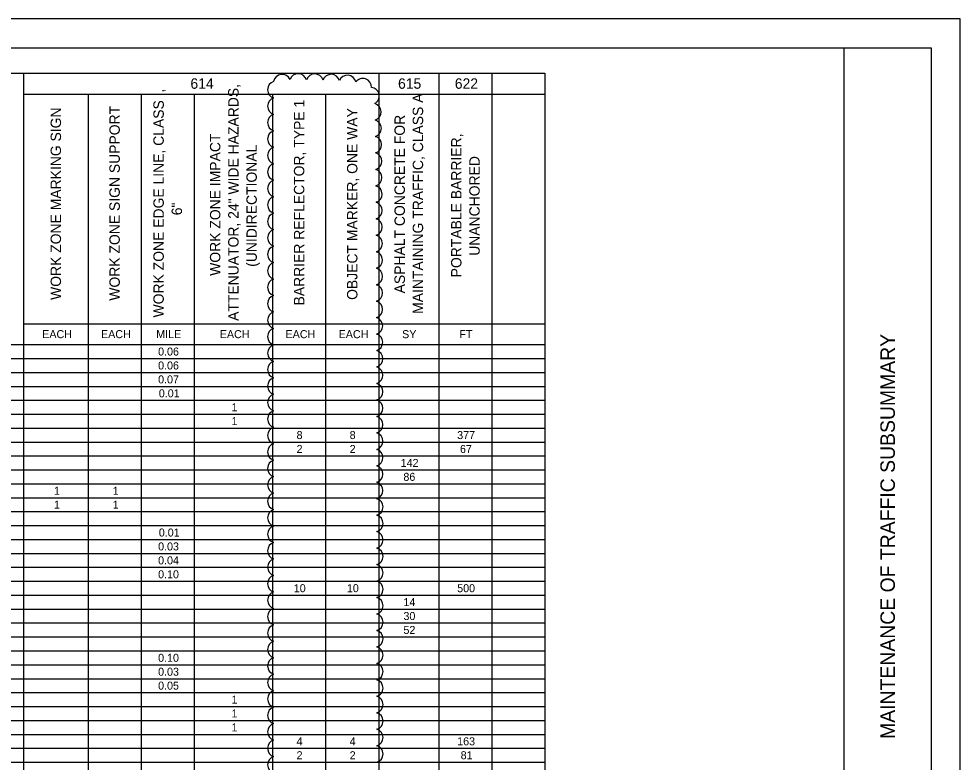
# Model space of a CAD drawing. Extents: x 0 to 35.9, y 0 to 22.
# Drawn here: x 17.78 to 34, y 9.18 to 22 of the extents above; entities that cross this region are included whole.
import ezdxf

# ---------------------------------------------------------------- set-up
doc = ezdxf.new("R2010")
doc.units = 0
for name, color, linetype in [('SC_Scratch2', 7, 'Continuous'), ('SH_Border', 7, 'Continuous'), ('SH_Cut_Line', 7, 'Continuous'), ('SH_Data', 7, 'Continuous'), ('SH_Text', 7, 'Continuous')]:
    doc.layers.add(name, color=color, linetype=linetype)

msp = doc.modelspace()

# ---------------------------------------------------------------- linework, layer by layer
at = {"layer": 'SC_Scratch2'}
for centre, start, end in [((22.315, 20.892), 23.859, 168.859), ((22.593, 20.905), 16.7934, 161.7934), ((22.877, 20.901), 16.6477, 161.6477), ((23.16, 20.894), 15.5399, 160.5399), ((23.441, 20.878), 12.7492, 157.7492), ((23.705, 20.822), 358.2571, 143.2571), ((22.214, 20.778), 107.5, 252.5), ((23.839, 20.669), 299.4005, 84.4005), ((22.214, 20.494), 107.5, 252.5), ((23.871, 20.396), 288.8288, 73.8288), ((22.214, 20.211), 107.5, 252.5), ((23.876, 20.113), 288.4136, 73.4136), ((22.214, 19.927), 107.5, 252.5), ((23.88, 19.829), 288.2088, 73.2088), ((22.214, 19.643), 107.5, 252.5), ((23.884, 19.545), 288.0806, 73.0806), ((22.214, 19.359), 107.5, 252.5), ((23.886, 19.261), 287.9905, 72.9905), ((22.214, 19.075), 107.5, 252.5), ((23.889, 18.978), 287.9228, 72.9228), ((22.214, 18.791), 107.5, 252.5), ((23.891, 18.694), 287.8694, 72.8694), ((22.214, 18.507), 107.5, 252.5), ((23.892, 18.41), 287.826, 72.826), ((22.214, 18.223), 107.5, 252.5), ((23.894, 18.126), 287.7897, 72.7897), ((22.214, 17.939), 107.5, 252.5), ((23.895, 17.842), 287.7588, 72.7588), ((22.214, 17.655), 107.5, 252.5), ((23.896, 17.558), 287.7321, 72.7321), ((22.214, 17.371), 107.5, 252.5), ((23.897, 17.274), 287.7088, 72.7088), ((22.214, 17.088), 107.5, 252.5), ((23.898, 16.99), 287.6881, 72.6881), ((22.214, 16.804), 107.5, 252.5), ((23.899, 16.707), 287.6696, 72.6696), ((22.214, 16.52), 107.5, 252.5), ((23.9, 16.423), 287.6529, 72.6529), ((22.214, 16.236), 107.5, 252.5), ((23.901, 16.139), 287.6378, 72.6378), ((22.214, 15.952), 107.5, 252.5), ((23.901, 15.855), 287.6241, 72.6241), ((22.214, 15.668), 107.5, 252.5), ((23.902, 15.571), 287.6114, 72.6114), ((22.214, 15.384), 107.5, 252.5), ((23.903, 15.287), 287.5998, 72.5998), ((22.214, 15.1), 107.5, 252.5), ((23.903, 15.003), 287.589, 72.589), ((22.214, 14.816), 107.5, 252.5), ((23.903, 14.719), 287.579, 72.579), ((22.214, 14.532), 107.5, 252.5), ((23.904, 14.435), 287.5697, 72.5697), ((22.214, 14.249), 107.5, 252.5), ((23.904, 14.151), 287.561, 72.561), ((22.214, 13.965), 107.5, 252.5), ((23.904, 13.868), 287.5528, 72.5528), ((22.214, 13.681), 107.5, 252.5), ((23.905, 13.584), 287.5451, 72.5451), ((22.214, 13.397), 107.5, 252.5), ((23.905, 13.3), 287.5378, 72.5378), ((22.214, 13.113), 107.5, 252.5), ((23.905, 13.016), 287.531, 72.531), ((22.214, 12.829), 107.5, 252.5), ((23.905, 12.732), 287.5245, 72.5245), ((22.214, 12.545), 107.5, 252.5), ((23.905, 12.448), 287.5184, 72.5184), ((22.214, 12.261), 107.5, 252.5), ((23.905, 12.164), 287.5125, 72.5125), ((22.214, 11.977), 107.5, 252.5), ((23.905, 11.88), 287.507, 72.507), ((22.214, 11.693), 107.5, 252.5), ((23.905, 11.596), 287.5018, 72.5018), ((22.214, 11.409), 107.5, 252.5), ((23.905, 11.312), 287.5, 72.5), ((22.214, 11.126), 107.5, 252.5), ((23.905, 11.029), 287.5, 72.5), ((22.214, 10.842), 107.5, 252.5), ((23.905, 10.745), 287.5, 72.5), ((22.214, 10.558), 107.5, 252.5), ((23.905, 10.461), 287.5, 72.5), ((22.214, 10.274), 107.5, 252.5), ((23.905, 10.177), 287.5, 72.5), ((22.214, 9.99), 107.5, 252.5), ((23.905, 9.893), 287.5, 72.5), ((22.214, 9.706), 107.5, 252.5), ((23.905, 9.609), 287.5, 72.5), ((22.214, 9.422), 107.5, 252.5), ((23.905, 9.325), 287.5, 72.5), ((22.214, 9.138), 107.5, 252.5)]:
    msp.add_arc(centre, 0.149, start, end, dxfattribs=at)
at = {"layer": 'SH_Border'}
msp.add_line((32, 0.5), (32, 21.5), dxfattribs=at)
msp.add_lwpolyline([(1.5, 21.5), (33.5, 21.5), (33.5, 0.5), (1.5, 0.5)], close=True, dxfattribs=at)
at = {"layer": 'SH_Cut_Line'}
msp.add_lwpolyline([(0, 0), (34, 0), (34, 22), (0, 22)], close=True, dxfattribs=at)
at = {"layer": 'SH_Text'}
for p, q in [((10.03, 21.063), (26.845, 21.063)), ((17.86, 21.063), (17.86, 0.888)), ((23.98, 21.063), (23.98, 0.888)), ((25.015, 21.063), (25.015, 0.888)), ((25.93, 21.063), (25.93, 0.888)), ((26.845, 21.063), (26.845, 0.888)), ((17.86, 20.703), (26.845, 20.703)), ((18.97, 20.703), (18.97, 0.888)), ((19.885, 20.703), (19.885, 0.888)), ((20.8, 20.703), (20.8, 0.888)), ((22.15, 20.703), (22.15, 0.888)), ((23.065, 20.703), (23.065, 0.888)), ((17.86, 16.743), (26.845, 16.743)), ((10.03, 16.383), (26.845, 16.383)), ((10.03, 16.143), (26.845, 16.143)), ((10.03, 15.903), (26.845, 15.903)), ((10.03, 15.663), (26.845, 15.663)), ((10.03, 15.423), (26.845, 15.423)), ((10.03, 15.183), (26.845, 15.183)), ((10.03, 14.943), (26.845, 14.943)), ((10.03, 14.703), (26.845, 14.703)), ((10.03, 14.463), (26.845, 14.463)), ((10.03, 14.223), (26.845, 14.223)), ((10.03, 13.983), (26.845, 13.983)), ((10.03, 13.743), (26.845, 13.743)), ((10.03, 13.503), (26.845, 13.503)), ((10.03, 13.263), (26.845, 13.263)), ((10.03, 13.023), (26.845, 13.023)), ((10.03, 12.783), (26.845, 12.783)), ((10.03, 12.543), (26.845, 12.543)), ((10.03, 12.303), (26.845, 12.303)), ((10.03, 12.063), (26.845, 12.063)), ((10.03, 11.823), (26.845, 11.823)), ((10.03, 11.583), (26.845, 11.583)), ((10.03, 11.343), (26.845, 11.343)), ((10.03, 11.103), (26.845, 11.103)), ((10.03, 10.863), (26.845, 10.863)), ((10.03, 10.623), (26.845, 10.623)), ((10.03, 10.383), (26.845, 10.383)), ((10.03, 10.143), (26.845, 10.143)), ((10.03, 9.903), (26.845, 9.903)), ((10.03, 9.663), (26.845, 9.663)), ((10.03, 9.423), (26.845, 9.423)), ((10.03, 9.183), (26.845, 9.183))]:
    msp.add_line(p, q, dxfattribs=at)

# ---------------------------------------------------------------- texts
at = {"layer": 'SH_Data'}
msp.add_text('MAINTENANCE OF TRAFFIC SUBSUMMARY', height=0.25, rotation=90, dxfattribs=at).set_placement((32.875, 9.584))
at = {"layer": 'SH_Text'}
for s, height, p in [('614', 0.1794, (20.735, 20.794)), ('615', 0.1794, (24.313, 20.794)), ('622', 0.1794, (25.291, 20.794)), ('EACH', 0.138, (18.181, 16.494)), ('EACH', 0.138, (19.194, 16.494)), ('MILE', 0.138, (20.145, 16.494)), ('EACH', 0.138, (21.241, 16.494)), ('EACH', 0.138, (22.374, 16.494)), ('EACH', 0.138, (23.289, 16.494)), ('SY', 0.138, (24.383, 16.494)), ('FT', 0.138, (25.369, 16.494)), ('0.06', 0.138, (20.178, 16.194)), ('0.06', 0.138, (20.178, 15.954)), ('0.07', 0.138, (20.178, 15.714)), ('0.01', 0.138, (20.19, 15.474)), ('1', 0.138, (21.443, 15.234)), ('1', 0.138, (21.443, 14.994)), ('8', 0.138, (22.564, 14.754)), ('8', 0.138, (23.479, 14.754)), ('377', 0.138, (25.332, 14.754)), ('2', 0.138, (22.564, 14.514)), ('2', 0.138, (23.479, 14.514)), ('67', 0.138, (25.38, 14.514)), ('142', 0.138, (24.358, 14.274)), ('86', 0.138, (24.405, 14.034)), ('1', 0.138, (18.383, 13.794)), ('1', 0.138, (19.396, 13.794)), ('1', 0.138, (18.383, 13.554)), ('1', 0.138, (19.396, 13.554)), ('0.01', 0.138, (20.19, 13.074)), ('0.03', 0.138, (20.178, 12.834)), ('0.04', 0.138, (20.178, 12.594)), ('0.10', 0.138, (20.178, 12.354)), ('10', 0.138, (22.516, 12.114)), ('10', 0.138, (23.431, 12.114)), ('500', 0.138, (25.332, 12.114)), ('14', 0.138, (24.406, 11.874)), ('30', 0.138, (24.406, 11.634)), ('52', 0.138, (24.406, 11.394)), ('0.10', 0.138, (20.178, 10.914)), ('0.03', 0.138, (20.178, 10.674)), ('0.05', 0.138, (20.178, 10.434)), ('1', 0.138, (21.443, 10.194)), ('1', 0.138, (21.443, 9.954)), ('1', 0.138, (21.443, 9.714)), ('4', 0.138, (22.564, 9.474)), ('4', 0.138, (23.479, 9.474)), ('163', 0.138, (25.332, 9.474)), ('2', 0.138, (22.564, 9.234)), ('2', 0.138, (23.479, 9.234)), ('81', 0.138, (25.392, 9.234))]:
    msp.add_text(s, height=height, dxfattribs=at).set_placement(p)
for s, p in [('WORK ZONE EDGE LINE, CLASS I, ', (20.276, 16.851)), ('ATTENUATOR, 24" WIDE HAZARDS, ', (21.565, 16.792)), ('MAINTAINING TRAFFIC, CLASS A', (24.745, 16.913)), ('WORK ZONE MARKING SIGN', (18.505, 17.153)), ('WORK ZONE SIGN SUPPORT', (19.518, 17.14)), ('BARRIER REFLECTOR, TYPE 1', (22.698, 17.058)), ('OBJECT MARKER, ONE WAY', (23.613, 17.154)), ('ASPHALT CONCRETE FOR ', (24.431, 17.266)), ('WORK ZONE IMPACT ', (21.251, 17.569)), ('PORTABLE BARRIER, ', (25.406, 17.543)), ('(UNIDIRECTIONAL', (21.879, 17.724)), ('UNANCHORED', (25.72, 17.914)), ('6"', (20.59, 18.613))]:
    msp.add_text(s, height=0.1794, rotation=90, dxfattribs=at).set_placement(p)

doc.saveas('drawing.dxf')
